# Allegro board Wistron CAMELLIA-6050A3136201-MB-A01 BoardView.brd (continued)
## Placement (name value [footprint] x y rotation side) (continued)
C4608  22uF_6.3V_3  [CLOONEY-6010B0219002-001]  143.28 68.92 270 top
C4609  22uF_6.3V_3  [CLOONEY-6010B0219002-001]  113.43 67.25 180 bottom
C4610  22uF_6.3V_3  [CLOONEY-6010B0219002-001]  140.84 68.92 270 top
C4611  22uF_6.3V_3  [CLOONEY-6010B0219002-001]  144.5 66.5 90 top
C4612  0.22uF_6.3V_1  [CSC_060X030X030_2]  253.62 14.94 90 top
C4613  0.22uF_6.3V_1  [CSC_060X030X030_2]  254.22 14.94 90 top
C4614  0.22uF_6.3V_1  [CSC_060X030X030_2]  250.62 14.94 90 top
C4615  0.22uF_6.3V_1  [CSC_060X030X030_2]  251.23 14.94 90 top
C4616  0.22uF_6.3V_1  [CSC_060X030X030_2]  251.89 56.05 270 top
C4617  0.22uF_6.3V_1  [CSC_060X030X030_2]  252.5 56.05 270 top
C4618  0.22uF_6.3V_1  [CSC_060X030X030_2]  254.94 56.05 270 top
C4619  0.22uF_6.3V_1  [CSC_060X030X030_2]  254.33 56.05 270 top
C4620  22uF_6.3V_3  [CLOONEY-6010B0219002-001]  145.81 64.15 270 top
C4621  22uF_6.3V_3  [CLOONEY-6010B0219002-001]  144.59 64.15 270 top
C4622  22uF_6.3V_3  [CLOONEY-6010B0219002-001]  145.72 66.5 90 top
C4623  22uF_6.3V_3  [CLOONEY-6010B0219002-001]  147.03 64.15 270 top
C4624  1uF_6.3V_1  [CSC_060X030X035_2]  166.34 77.3 0 top
C4625  10uF_6.3V_2  [CSC_100X050X070_2]  163.7 89.09 180 top
C4626  22uF_6.3V_3  [CSC_160X080X100_2]  166.7 76.39 0 top
C4627  0.1uF_6.3V_1  [CSC_060X030X030_2]  204.11 64.45 90 bottom
C4628  22uF_6.3V_3  [CLOONEY-6010B0219002-001]  152.83 69.38 270 top
C4629  22uF_6.3V_3  [CLOONEY-6010B0219002-001]  123.72 90.87 270 top
C4630  22uF_6.3V_3  [CLOONEY-6010B0219002-001]  154.78 63.89 180 top
C4631  22uF_6.3V_3  [CLOONEY-6010B0219002-001]  146.96 89.85 270 top
C4632  0.22uF_6.3V_1  [CSC_060X030X030_2]  256.77 56.05 270 top
C4633  0.22uF_6.3V_1  [CSC_060X030X030_2]  257.37 56.05 270 top
C4634  0.22uF_6.3V_1  [CSC_060X030X030_2]  259.23 56.05 270 top
C4635  0.22uF_6.3V_1  [CSC_060X030X030_2]  259.84 56.05 270 top
C4636  22uF_6.3V_3  [CLOONEY-6010B0219002-001]  154.78 69.98 180 top
C4637  22uF_6.3V_3  [CLOONEY-6010B0219002-001]  143.15 89.85 270 top
C4638  22uF_6.3V_3  [CLOONEY-6010B0219002-001]  154.78 68.76 180 top
C4639  22uF_6.3V_3  [CLOONEY-6010B0219002-001]  157.12 94.68 0 top
C4640  22uF_6.3V_3  [CLOONEY-6010B0219002-001]  144.42 89.85 270 top
C4641  22uF_6.3V_3  [CLOONEY-6010B0219002-001]  151.61 69.38 270 top
C4642  22uF_6.3V_3  [CLOONEY-6010B0219002-001]  157.12 93.41 0 top
C4643  22uF_6.3V_3  [CLOONEY-6010B0219002-001]  150.39 69.38 270 top
C4644  22uF_6.3V_3  [CLOONEY-6010B0219002-001]  145.69 89.85 270 top
C4645  22uF_6.3V_3  [CLOONEY-6010B0219002-001]  142.15 61.82 90 top
C4646  22uF_6.3V_3  [CLOONEY-6010B0219002-001]  147.03 61.82 90 top
C4647  22uF_6.3V_3  [CLOONEY-6010B0219002-001]  144.59 61.82 90 top
C4648  22uF_6.3V_3  [CLOONEY-6010B0219002-001]  145.81 61.82 90 top
C4649  10uF_6.3V_3  [RANGERS-6010B0044902-001]  143.37 61.82 90 top
C4650  0.1uF_6.3V_1  [CSC_060X030X030_2]  204.75 64.45 90 bottom
C4651  0.1uF_6.3V_1  [CSC_060X030X030_2]  74.34 28.39 0 bottom
C4652  0.1uF_6.3V_1  [CSC_060X030X030_2]  74.34 27.75 0 bottom
C4764  1uF_6.3V_1  [CSC_060X030X035_2]  222.48 53.05 90 bottom
C4766  1uF_6.3V_1  [CSC_060X030X035_2]  222.73 53.91 180 bottom
C4767  12pF_50V_1  [CSC_060X030X030_2]  204.06 49.57 90 bottom
C4768  1uF_6.3V_1  [CSC_060X030X035_2]  220.82 51.37 270 bottom
C4788  12pF_50V_1  [CSC_060X030X030_2]  204.06 50.71 270 bottom
C4818  0.22uF_6.3V_1  [CSC_060X030X030_2]  259.63 14.94 90 top
C4819  0.22uF_6.3V_1  [CSC_060X030X030_2]  260.24 14.94 90 top
C4820  0.22uF_6.3V_1  [CSC_060X030X030_2]  256.64 14.94 90 top
C4821  0.22uF_6.3V_1  [CSC_060X030X030_2]  257.25 14.94 90 top
C4826  15pF_25V_1  [CSC_060X030X033_2]  188.64 76.13 90 bottom
C4828  12pF_50V_1  [CSC_060X030X030_2]  188.64 74.98 270 bottom
C4920  1uF_6.3V_2_NP  [CSC_100X050X055_2_NP]  102.64 41.72 0 top
C4921  1uF_6.3V_2_NP  [CSC_100X050X055_2_NP]  99.46 41.72 0 top
C4937  0.1uF_10V_1  [CSC_060X030X030_2]  125.37 72.35 90 top
C6035  1000pF_25V_1  [CSC_060X030X030_2]  232 80.66 180 bottom
C6037  1000pF_25V_1  [CSC_060X030X030_2]  233.4 79.29 180 bottom
C6038  0.01UF_25V_1  [CSC_060X030X033_2]  234.51 79.37 180 bottom
C7000  1uF_6.3V_1  [CSC_060X030X035_2]  212.24 87.7 180 bottom
C7001  0.22uF_6.3V_1  [CSC_060X030X030_2]  214.27 93.79 180 bottom
C7002  1uF_6.3V_1  [CSC_060X030X035_2]  212.49 83.63 0 bottom
C7003  10uF_6.3V_3  [RANGERS-6010B0044902-001]  197.05 91.68 270 bottom
C7004  0.1uF_6.3V_1  [CSC_060X030X030_2]  211.1 87.7 180 bottom
C7005  10uF_6.3V_3  [RANGERS-6010B0044902-001]  209.7 87.44 270 bottom
C7006  0.1uF_6.3V_1  [CSC_060X030X030_2]  199.42 88.98 0 bottom
C7007  0.1uF_6.3V_1  [CSC_060X030X030_2]  211.35 83.63 0 bottom
C7008  10uF_6.3V_3  [RANGERS-6010B0044902-001]  208.52 84.27 180 bottom
C7009  0.01UF_25V_1  [CSC_060X030X033_2]  212.35 76.65 90 bottom
C7010  0.1uF_6.3V_1  [CSC_060X030X030_2]  195.73 94.15 180 bottom
C7012  0.1uF_6.3V_1  [CSC_060X030X030_2]  213.76 91.25 90 bottom
C7013  4.7uF_6.3V_3  [CSC_160X080X090_2]  215.29 91.25 0 bottom
C7023  0.1uF_25V_1  [CSC_060X030X033_2]  158.65 97.73 180 bottom
C7024  0.1uF_6.3V_1  [CSC_060X030X030_2]  208.73 76.77 90 bottom
C7025  3300pF_50V_2  [CSC_100X050X040_2]  161.41 87.06 90 bottom
C7027  0.01UF_25V_1  [CSC_060X030X033_2]  161.46 88.48 270 bottom
C7029  0.01uF_25V_2  [CSC_100X050X040_2]  169.19 42.23 90 top
C7040  220pF_50V_1  [CSC_060X030X033_2]  208.68 85.92 0 bottom
C7041  220pF_50V_1  [CSC_060X030X033_2]  208.68 85.28 180 bottom
C7400  0.01UF_25V_1  [CSC_060X030X033_2]  213.48 70.3 270 bottom
C7401  3300pF_50V_2  [CSC_100X050X040_2]  216.56 74.61 0 bottom
C7402  1000pF_25V_1  [CSC_060X030X030_2]  212.24 74.82 270 bottom
C7403  0.22uF_6.3V_1  [CSC_060X030X030_2]  208.02 73.6 90 bottom
C7406  1uF_6.3V_1  [CSC_060X030X035_2]  226.36 36.13 270 top
C7500  100pF_50V_1  [CSC_060X030X030_2]  85.95 28.11 270 bottom
C7501  100pF_50V_1  [CSC_060X030X030_2]  87.09 28.11 270 bottom
C7502  0.1uF_25V_2  [CSC_100X050X040_2]  86.05 24.83 0 bottom
C7503  100pF_50V_1  [CSC_060X030X030_2]  79.56 25.97 0 bottom
C7504  470PF_50V_1  [CSC_060X030X033_2]  267.2 47.56 180 bottom
C7505  18pF_50V_1  [CSC_060X030X030_2]  209.98 61.61 180 bottom
C7506  18pF_50V_1  [CSC_060X030X030_2]  208.86 61.61 0 bottom
C7507  18pF_50V_1  [CSC_060X030X030_2]  211.88 63.59 90 bottom
C7508  1uF_6.3V_1  [CSC_060X030X035_2]  229.13 7.94 0 top
C7511  68pF_50V_1  [CSC_060X030X033_2]  145.06 113.35 180 top
C7512  68pF_50V_1  [CSC_060X030X033_2]  148.49 5.65 0 top
C7513  68pF_50V_1  [CSC_060X030X033_2]  129.94 2.61 270 top
C7514  68pF_50V_1  [CSC_060X030X033_2]  189.38 99 0 top
C7515  68pF_50V_1  [CSC_060X030X033_2]  214.14 79.57 270 top
C7516  68pF_50V_1  [CSC_060X030X033_2]  122.7 113.35 0 top
C7517  68pF_50V_1  [CSC_060X030X033_2]  62.38 11.62 0 top
C7518  68pF_50V_1  [CSC_060X030X033_2]  155.85 2.35 0 top
C7519  68pF_50V_1  [CSC_060X030X033_2]  212.75 99.51 0 top
C7520  10pF_50V_1  [CSC_060X030X030_2]  57.81 32.96 0 bottom
C7521  68pF_50V_1  [CSC_060X030X033_2]  57.81 33.59 0 bottom
C7522  100pF_50V_1  [CSC_060X030X030_2]  57.81 32.32 0 bottom
C7523  10pF_50V_1  [CSC_060X030X030_2]  125.9 90.79 270 top
C7524  68pF_50V_1  [CSC_060X030X033_2]  126.51 90.79 270 top
C7525  100pF_50V_1  [CSC_060X030X030_2]  127.12 90.79 270 top
C7526  10pF_50V_1  [CSC_060X030X030_2]  135.3 90.79 270 top
C7527  68pF_50V_1  [CSC_060X030X033_2]  135.91 90.79 270 top
C7528  100pF_50V_1  [CSC_060X030X030_2]  136.52 90.79 270 top
C7529  10pF_50V_1  [CSC_060X030X030_2]  153.62 61.58 180 top
C7530  CSC0201  [CSC_060X030X030_2]  227 36.13 270 top
C7531  68pF_50V_1  [CSC_060X030X033_2]  153.62 60.97 180 top
C7532  100pF_50V_1  [CSC_060X030X030_2]  153.62 60.36 180 top
C7533  10pF_50V_1  [CSC_060X030X030_2]  145.31 111.26 180 bottom
C7534  68pF_50V_1  [CSC_060X030X033_2]  145.31 116.47 180 bottom
C7535  100pF_50V_1  [CSC_060X030X030_2]  145.31 110.66 180 bottom
C7536  6.8PF_50V_1  [CSC_060X030X033_2]  163.6 29.15 180 top
C7537  6.8PF_50V_1  [CSC_060X030X033_2]  217.32 21.53 90 top
C7538  6.8PF_50V_1  [CSC_060X030X033_2]  162.84 27.88 0 top
C7539  6.8PF_50V_1  [CSC_060X030X033_2]  142.01 55.56 180 top
C7540  6.8PF_50V_1  [CSC_060X030X033_2]  219.35 21.66 90 top
C7541  6.8PF_50V_1  [CSC_060X030X033_2]  175.54 21.53 90 top
C7542  6.8PF_50V_1  [CSC_060X030X033_2]  145.95 18.61 270 top
C7543  6.8PF_50V_1  [CSC_060X030X033_2]  183.41 23.18 270 top
C7544  6.8PF_50V_1  [CSC_060X030X033_2]  191.41 13.91 0 top
C7545  6.8PF_50V_1  [CSC_060X030X033_2]  97.81 23.43 270 top
C7546  6.8PF_50V_1  [CSC_060X030X033_2]  231.92 17.85 180 top
C7547  6.8PF_50V_1  [CSC_060X030X033_2]  149.37 11.88 270 top
C7548  6.8PF_50V_1  [CSC_060X030X033_2]  154.33 55.43 90 top
C7549  6.8PF_50V_1  [CSC_060X030X033_2]  143.28 21.53 90 top
C7550  6.8PF_50V_1  [CSC_060X030X033_2]  193.82 21.53 90 top
C7551  6.8PF_50V_1  [CSC_060X030X033_2]  187.6 21.66 90 top
C7552  6.8PF_50V_1  [CSC_060X030X033_2]  112.16 21.91 90 top
C7553  6.8PF_50V_1  [CSC_060X030X033_2]  225.07 21.4 90 top
C7554  6.8PF_50V_1  [CSC_060X030X033_2]  141.37 19.24 270 top
C7555  10pF_50V_1  [CSC_060X030X030_2]  182.52 103.95 270 bottom
C7556  68pF_50V_1  [CSC_060X030X033_2]  183.16 103.95 270 bottom
C7557  0.1uF_25V_1  [CSC_060X030X033_2]  183.79 103.95 270 bottom
C7558  10pF_50V_1  [CSC_060X030X030_2]  170.58 94.93 0 bottom
C7559  68pF_50V_1  [CSC_060X030X033_2]  170.58 95.57 0 bottom
C7560  100pF_50V_1  [CSC_060X030X030_2]  170.58 96.2 0 bottom
C7561  10pF_50V_1  [CSC_060X030X030_2]  115.44 89.14 225 bottom
C7562  68pF_50V_1  [CSC_060X030X033_2]  115.87 88.71 225 bottom
C7563  100pF_50V_1  [CSC_060X030X030_2]  116.3 88.28 225 bottom
C7564  100pF_50V_1  [CSC_060X030X030_2]  181.07 102.48 180 bottom
C7565  100pF_50V_1  [CSC_060X030X030_2]  181.07 101.87 180 bottom
C7566  100pF_50V_1  [CSC_060X030X030_2]  181.07 99.79 180 bottom
C7567  10pF_50V_1  [CSC_060X030X030_2]  228.01 86.32 0 bottom
C7568  68pF_50V_1  [CSC_060X030X033_2]  228.01 86.93 0 bottom
C7600  0.1uF_25V_2  [CSC_100X050X040_2]  272.16 33.21 270 top
C7601  0.1uF_25V_2  [CSC_100X050X040_2]  268.37 38.8 90 top
C7602  0.22uF_25V_1  [CSC_060X030X033_2]  269.14 38.55 90 top
C7603  0.22uF_25V_1  [CSC_060X030X033_2]  272.92 33.47 270 top
C7604  0.1uF_25V_2  [CSC_100X050X040_2]  274.72 93.92 90 top
C7605  0.1uF_25V_2  [CSC_100X050X040_2]  269.62 81.07 180 top
C7606  0.22uF_25V_1  [CSC_060X030X033_2]  273.96 93.92 90 top
C7607  0.22uF_25V_1  [CSC_060X030X033_2]  269.49 80.3 180 top
C7608  0.1uF_25V_2  [CSC_100X050X040_2]  199.92 97.6 90 top
C7609  0.1uF_25V_2  [CSC_100X050X040_2]  162.33 95.95 180 top
C7610  0.1uF_25V_2  [CSC_100X050X040_2]  103.65 6.92 0 top
C7611  0.1uF_10V_1  [CSC_060X030X030_2]  267.31 80.38 90 top
C7612  0.1uF_10V_1  [CSC_060X030X030_2]  215.29 53.15 270 top
C7613  0.1uF_10V_1  [CSC_060X030X030_2]  219.73 100.78 90 top
C7614  0.1uF_10V_1  [CSC_060X030X030_2]  55.27 22.67 90 top
C7615  0.1uF_10V_1  [CSC_060X030X030_2]  54.84 9.65 270 top
C7616  0.1uF_10V_1  [CSC_060X030X030_2]  200.68 115.38 0 top
C7617  0.1uF_10V_1  [CSC_060X030X030_2]  31.26 45.4 0 top
C7618  0.1uF_10V_1  [CSC_060X030X030_2]  267.61 86.17 0 top
C7619  0.1uF_10V_1  [CSC_060X030X030_2]  76.98 31.94 90 top
C7620  0.1uF_10V_1  [CSC_060X030X030_2]  26.31 21.53 90 top
C7621  0.1uF_10V_1  [CSC_060X030X030_2]  56.13 25.09 270 top
C7622  0.1uF_10V_1  [CSC_060X030X030_2]  238.12 28.01 0 top
C7623  0.01UF_25V_1  [CSC_060X030X033_2]  232.86 80.51 270 bottom
C7624  10pF_50V_1  [CSC_060X030X030_2]  24.56 33.26 270 top
C7625  10pF_50V_1  [CSC_060X030X030_2]  25.78 37.28 0 top
C7626  1000pF_25V_1  [CSC_060X030X030_2]  273.35 93.92 90 top
C7627  1000pF_25V_1  [CSC_060X030X030_2]  269.74 38.55 90 top
C7628  0.1uF_25V_2  [CSC_100X050X040_2]  251.1 93.03 90 bottom
C9200  0.1uF_16V_2  [CSC_100X050X040_2]  37.54 109.21 270 top
C9201  0.1uF_16V_2  [CSC_100X050X040_2]  42.21 104.21 180 top
C9202  0.1uF_16V_2  [CSC_100X050X040_2]  42.21 105.09 180 top
C9203  0.01uF_50V_2  [CSC_100X050X040_2]  35.96 101.16 90 top
C9204  0.1uF_16V_2  [CSC_100X050X040_2]  34.19 100.34 270 top
C9205  1uF_6.3V_2  [CSC_100X050X055_2]  35.07 101.16 90 top
C9206  10uF_6.3V_3  [CSC_160X080X095_2]  34.97 108.8 90 top
C9207  10uF_6.3V_3  [RANGERS-6010B0044902-001]  34.57 88.71 90 top
C9208  100uF_6.3V  [CST_320X160X180_2_245]  41.68 106.21 90 bottom
C9209  0.1uF_16V_2  [CSC_100X050X040_2]  37.78 89.09 90 top
C9210  0.1uF_16V_2  [CSC_100X050X040_2]  38.67 89.09 90 top
C9211  0.1uF_16V_2  [CSC_100X050X040_2]  41.17 89.22 90 top
C9212  0.1uF_16V_2  [CSC_100X050X040_2]  40.28 89.22 90 top
C9213  0.1uF_16V_2  [CSC_100X050X040_2]  35.71 88.33 90 top
C9214  0.1uF_16V_2  [CSC_100X050X040_2]  43.33 87.44 270 top
C9215  0.1uF_16V_2  [CSC_100X050X040_2]  42.44 87.44 270 top
C9216  0.01uF_50V_2  [CSC_100X050X040_2]  37.11 81.98 90 top
C9217  0.1uF_16V_2  [CSC_100X050X040_2]  38 81.98 90 top
C9218  1uF_6.3V_2  [CSC_100X050X055_2]  38.88 81.98 90 top
C9222  0.1uF_16V_2  [CSC_100X050X040_2]  40.18 69.92 90 top
C9223  0.1uF_16V_2  [CSC_100X050X040_2]  39.29 69.92 90 top
C9224  0.1uF_16V_2  [CSC_100X050X040_2]  41.07 69.92 90 top
C9225  0.1uF_16V_2  [CSC_100X050X040_2]  41.96 69.92 90 top
C9226  100pF_50V_1  [CSC_060X030X030_2]  27.15 74.08 270 top
C9227  100pF_50V_1  [CSC_060X030X030_2]  30.12 68.14 90 top
C9228  100pF_50V_1  [CSC_060X030X030_2]  30.1 73.88 90 top
C9229  0.1uF_10V_1  [CSC_060X030X030_2]  42.77 102.49 0 bottom
C9300  0.1uF_10V_1  [CSC_060X030X030_2]  77.14 108.42 180 top
C9301  0.1uF_10V_1  [CSC_060X030X030_2]  77.5 106.07 180 top
C9302  0.1uF_10V_1  [CSC_060X030X030_2]  75.34 79.06 0 top
C9353  4.7UF_6.3V_2  [CSC_100X050X065_2]  61.69 66.87 0 top
C9354  1000pF_25V_1  [CSC_060X030X030_2]  61.49 67.88 0 top
C9357  4.7UF_6.3V_2  [CSC_100X050X065_2]  61.57 65.98 0 top
C9360  1000pF_25V_1  [CSC_060X030X030_2]  60.6 64.58 0 top
C60000  68uF_16V  [CS_730X430X200_2_610]  145.02 113.86 180 bottom
C60001  4.7uF_25V_5  [CSC_200X125X135_2]  153.4 113.93 90 bottom
C60002  4.7uF_25V_5  [CSC_200X125X135_2]  151.75 113.93 90 bottom
C60003  2.2uF_25V_3  [CSC_160X080X095_2]  150.3 114.21 90 bottom
C60004  2.2uF_25V_3  [CSC_160X080X095_2]  154.84 116.04 90 bottom
C60006  0.022uF_16V_2  [CSC_100X050X040_2]  187.52 102.17 180 top
C60007  CSC0402  [CSC_100X050X040_2]  188.77 101.64 270 top
C60008  2.2UF_6.3V_2  [CSC_100X050X055_2]  184.05 108.78 270 top
C60009  4.7uF_25V_3  [CSC_160X080X095_2]  199.92 111.19 90 bottom
C60010  10UF_25V_5  [CSC_200X125X140_2]  183.16 109.03 90 bottom
C60011  4.7uF_25V_5  [CSC_200X125X135_2]  177.95 108.02 90 bottom
C60012  CSC0805  [CSC_200X125X130_2]  179.98 104.33 270 bottom
C60013  CSC0603  [CSC_160X080X080_2]  181.51 104.46 270 bottom
C60014  1uF_25V_3  [CSC_160X080X080_2]  178.33 104.33 270 bottom
C60015  0.22uF_25V_3  [CSC_160X080X080_2]  194.84 111.95 90 top
C60016  CSC0402  [CSC_100X050X040_2]  175.08 115.97 0 bottom
C60017  10UF_25V_5  [CSC_200X125X140_2]  113.56 114.75 90 bottom
C60018  CSC0402  [CSC_100X050X040_2]  199.03 100.4 270 top
C60019  CSC0402  [CSC_100X050X040_2]  196.24 99.89 180 top
C60020  0.022uF_16V_2  [CSC_100X050X040_2]  191.77 97.58 180 top
C60021  CSC0402  [CSC_100X050X040_2]  199.92 112.71 90 top
C60022  2.2UF_6.3V_3  [CSC_160X080X090_2]  196.11 111.95 90 top
C60023  1UF_25V_2  [CSC_100X050X055_2]  197.13 106.75 270 top
C60024  CSC0402  [CSC_100X050X040_2]  199.03 112.71 90 top
C60025  0.22uF_25V_3  [CSC_160X080X080_2]  197.13 110.17 0 top
C60026  CSC0402  [CSC_100X050X040_2]  157.38 116.27 180 top
C60027  1000PF_50V_2  [CSC_100X050X055_2]  193.82 97.6 0 top
C60028  1UF_25V_2  [CSC_100X050X055_2]  189.25 113.25 90 top
C60029  CSC0402  [CSC_100X050X040_2]  188.87 111.85 180 top
C60030  CSC0402  [CSC_100X050X040_2]  193.67 113.78 0 top
C60031  CSC0402  [CSC_100X050X040_2]  197.25 98.92 0 top
C60032  10UF_25V_5  [CSC_200X125X140_2]  115.21 114.75 90 bottom
C60033  CSC0402  [CSC_100X050X040_2]  190.45 98.87 270 top
C60034  1UF_25V_2  [CSC_100X050X055_2]  245.51 97.58 270 top
C60035  2.2UF_6.3V_3  [CSC_160X080X090_2]  180.95 111.8 180 top
C60048  1uF_25V_3  [CSC_160X080X080_2]  241.88 80.68 0 bottom
C60049  10pF_50V_2  [CSC_100X050X040_2]  188.62 103.06 180 top
C60050  CSC0402  [CSC_100X050X040_2]  86.05 25.77 0 bottom
C60099  15uF_25V  [CS_350X280X200_2]  180.5 110.14 90 bottom
C60101  22uF_6.3V_3  [CSC_160X080X100_2]  229 66.36 0 bottom
C60102  22uF_6.3V_3  [CSC_160X080X100_2]  229 70.17 0 bottom
C60103  22uF_6.3V_3  [CSC_160X080X100_2]  229 68.9 0 bottom
C60104  22uF_6.3V_3  [CSC_160X080X100_2]  229 67.63 0 bottom
C60109  1uF_6.3V_2  [CSC_100X050X055_2]  224.69 80.33 270 bottom
C60110  10UF_25V_5  [CSC_200X125X140_2]  228.01 85.18 0 bottom
C60111  4.7uF_25V_3  [CSC_160X080X095_2]  228.18 83.62 0 bottom
C60112  0.1uF_25V_2  [CSC_100X050X040_2]  228.03 82.29 0 bottom
C60115  0.1uF_16V_2  [CSC_100X050X040_2]  223.29 77.54 270 bottom
C60116  CSC0402  [CSC_100X050X040_2]  231.26 75.22 270 bottom
C60190  0.1uF_16V_2  [CSC_100X050X040_2]  231.21 79.72 0 bottom
C60191  1uF_6.3V_2  [CSC_100X050X055_2]  231.21 78.83 0 bottom
C60200  1000PF_50V_2  [CSC_100X050X055_2]  241.75 76.57 270 bottom
C60201  22UF_6.3V_5  [CSC_200X125X140_2]  239.43 63.4 270 bottom
C60202  22UF_6.3V_5  [CSC_200X125X140_2]  237.78 63.4 270 bottom
C60203  22UF_6.3V_5  [CSC_200X125X140_2]  236.13 63.4 270 bottom
C60204  22UF_6.3V_5  [CSC_200X125X140_2]  234.35 63.4 270 bottom
C60205  100uF_6.3V  [CST_320X160X180_2_245]  234.34 64 270 bottom
C60209  4.7UF_6.3V_2  [CSC_100X050X065_2]  241.8 72.66 0 bottom
C60210  10UF_25V_5  [CSC_200X125X140_2]  237.89 78.31 0 bottom
C60211  10uF_25V_3  [CSC_160X080X090_2]  237.89 79.75 0 bottom
C60212  0.1uF_25V_2  [CSC_100X050X040_2]  237.77 77.04 0 bottom
C60215  0.1uF_16V_2  [CSC_100X050X040_2]  233.58 71.69 0 bottom
C60216  CSC0402  [CSC_100X050X040_2]  233.58 70.8 180 bottom
C60217  4.7UF_6.3V_2  [CSC_100X050X065_2]  241.8 73.55 0 bottom
C60250  22UF_6.3V_5  [CSC_200X125X140_2]  191.46 86.73 270 bottom
C60251  22UF_6.3V_5  [CSC_200X125X140_2]  189.81 86.73 270 bottom
C60252  22UF_6.3V_5  [CSC_200X125X140_2]  185.57 86.73 270 bottom
C60253  22UF_6.3V_5  [CSC_200X125X140_2]  188.16 86.73 270 bottom
C60254  100uF_6.3V  [CST_320X160X180_2_245]  185.57 86.3 270 bottom
C60259  4.7UF_6.3V_2  [CSC_100X050X065_2]  192.5 96.23 270 bottom
C60260  4.7uF_25V_5  [CSC_200X125X135_2]  187.09 101.16 90 bottom
C60261  4.7uF_25V_5  [CSC_200X125X135_2]  185.32 101.16 90 bottom
C60262  0.1uF_25V_2  [CSC_100X050X040_2]  188.49 100.78 90 bottom
C60263  15uF_25V  [CS_350X280X200_2]  160.47 106.39 0 bottom
C60265  0.1uF_16V_2  [CSC_100X050X040_2]  185.82 96.33 0 bottom
C60266  CSC0402  [CSC_100X050X040_2]  184.43 91.25 270 bottom
C60280  4.7UF_6.3V_2  [CSC_100X050X065_2]  193.39 96.61 270 bottom
C60281  1000PF_50V_2  [CSC_100X050X055_2]  194.07 98.74 180 bottom
C60300  22uF_6.3V_3  [CSC_160X080X100_2]  170.33 3.09 270 bottom
C60301  22uF_6.3V_3  [CSC_160X080X100_2]  172.77 3.09 270 bottom
C60302  22uF_6.3V_3  [CSC_160X080X100_2]  167.94 8.27 180 bottom
C60303  CSC0603  [CSC_160X080X080_2]  171.55 3.09 270 bottom
C60304  CSC0603  [CSC_160X080X080_2]  173.99 3.09 270 bottom
C60309  1uF_6.3V_2  [CSC_100X050X055_2]  156.99 7.69 0 top
C60310  10uF_25V_3  [CSC_160X080X090_2]  152.88 6.16 90 bottom
C60311  10UF_25V_5  [CSC_200X125X140_2]  154.33 6.16 90 bottom
C60312  0.1uF_25V_2  [CSC_100X050X040_2]  155.67 6.19 90 bottom
C60313  10uF_25V_3  [CSC_160X080X090_2]  154.33 6.16 90 bottom
C60315  0.1uF_16V_2  [CSC_100X050X040_2]  161.52 1.72 0 bottom
C60316  CSC0402  [CSC_100X050X040_2]  165.96 8.12 0 bottom
C60348  CSC0402  [CSC_100X050X040_2]  159.01 1.67 0 bottom
C60350  22uF_6.3V_3  [CSC_160X080X100_2]  158.03 9.76 0 top
C60351  0.22uF_6.3V_2  [CSC_100X050X040_2]  158.65 7.69 180 top
C60400  22uF_6.3V_3  [CSC_160X080X100_2]  204.85 4.26 270 bottom
C60401  22uF_6.3V_3  [CLOONEY-6010B0219002-001]  203.58 4.26 270 bottom
C60405  22pF_50V_2  [CSC_100X050X040_2]  194.38 7.69 270 bottom
C60410  10uF_6.3V_3  [CSC_160X080X095_2]  192.78 3.75 0 bottom
C60500  22uF_6.3V_3  [CSC_160X080X100_2]  115.22 55.51 90 bottom
C60501  22uF_6.3V_3  [CSC_160X080X100_2]  116.44 54.8 90 bottom
C60502  22uF_6.3V_3  [CSC_160X080X100_2]  117.66 54.8 90 bottom
C60509  1uF_6.3V_2  [CSC_100X050X055_2]  102.71 51.07 270 bottom
C60510  10UF_25V_5  [CSC_200X125X140_2]  100.48 54.36 90 bottom
C60511  0.1uF_25V_2  [CSC_100X050X040_2]  101.83 54.38 90 bottom
C60515  0.1uF_16V_2  [CSC_100X050X040_2]  106.78 50.61 90 bottom
C60516  CSC0402  [CSC_100X050X040_2]  110.54 57.66 0 bottom
C60600  22uF_6.3V_3  [CSC_160X080X100_2]  117.62 94.81 45 bottom
C60601  22uF_6.3V_3  [CSC_160X080X100_2]  118.51 93.92 45 bottom
C60602  22uF_6.3V_3  [CSC_160X080X100_2]  114.2 89.35 225 bottom
C60603  CSC0603  [CSC_160X080X080_2]  112.42 91.12 225 bottom
C60604  CSC0603  [CSC_160X080X080_2]  113.31 90.24 225 bottom
C60609  4.7UF_6.3V_2  [CSC_100X050X065_2]  109.8 100.47 225 bottom
C60610  10UF_25V_5  [CSC_200X125X140_2]  104.16 104.33 45 bottom
C60611  CSC0805  [CSC_200X125X130_2]  102.89 105.6 45 bottom
C60612  0.1uF_25V_2  [CSC_100X050X040_2]  105.05 103.32 45 bottom
C60615  0.1uF_16V_2  [CSC_100X050X040_2]  106.45 97.98 45 bottom
C60616  CSC0402  [CSC_100X050X040_2]  110 92.9 315 bottom
C60620  220pF_50V_2  [CSC_100X050X040_2]  109.12 104.71 225 bottom
C60630  1uF_6.3V_2  [CSC_100X050X055_2]  110.26 102.17 315 bottom
C60900  22uF_6.3V_3  [CSC_160X080X100_2]  171.22 92.14 0 bottom
C60901  22uF_6.3V_3  [CSC_160X080X100_2]  171.22 90.87 0 bottom
C60902  22uF_6.3V_3  [CSC_160X080X100_2]  171.22 89.6 0 bottom
C60903  CSC0603  [CSC_160X080X080_2]  171.22 88.33 0 bottom
C60904  CSC0603  [CSC_160X080X080_2]  171.22 93.41 0 bottom
C60909  4.7UF_6.3V_2  [CSC_100X050X065_2]  168.68 98.85 270 bottom
C60910  10UF_25V_5  [CSC_200X125X140_2]  163.78 103.34 90 bottom
C60911  CSC0805  [CSC_200X125X130_2]  162.12 103.34 90 bottom
C60912  0.1uF_25V_2  [CSC_100X050X040_2]  165.07 103.21 90 bottom
C60915  0.1uF_16V_2  [CSC_100X050X040_2]  162.71 98.62 0 bottom
C60916  CSC0402  [CSC_100X050X040_2]  162.46 94.93 270 bottom
C60920  330pF_50V_2  [CSC_100X050X040_2]  169.54 101.84 270 bottom
C60930  1uF_6.3V_2  [CSC_100X050X055_2]  169.92 99.68 0 bottom
C61400  22uF_6.3V_3  [CSC_160X080X100_2]  173.76 92.14 180 bottom
C61401  22uF_6.3V_3  [CSC_160X080X100_2]  173.76 90.87 180 bottom
C61402  22uF_6.3V_3  [CSC_160X080X100_2]  173.76 89.6 180 bottom
C61409  1uF_6.3V_2  [CSC_100X050X055_2]  174.93 96.71 270 bottom
C61410  10UF_25V_5  [CSC_200X125X140_2]  178.07 100.43 0 bottom
C61411  0.1uF_25V_2  [CSC_100X050X040_2]  178.33 98.98 0 bottom
C61415  0.1uF_16V_2  [CSC_100X050X040_2]  174.39 93.83 270 bottom
C61416  CSC0402  [CSC_100X050X040_2]  183.03 91.25 270 bottom
C61700  10uF_6.3V_3  [CSC_160X080X095_2]  232.27 89.94 90 bottom
C61705  330pF_50V_2  [CSC_100X050X040_2]  227 92.04 180 bottom
C61710  4.7uF_6.3V_3  [CSC_160X080X090_2]  224.94 87.67 0 bottom
C66000  330uF_2V_9mR_Pana_-35%  [CS_730X430X210_2]  139.01 95.7 90 bottom
C66001  22uF_6.3V_3  [CSC_160X080X100_2]  134.39 90.87 270 top
C66002  22uF_6.3V_3  [CSC_160X080X100_2]  141.25 91.28 270 top
C66003  22uF_6.3V_3  [CSC_160X080X100_2]  162.02 63.88 0 top
C66004  22uF_6.3V_3  [CSC_160X080X100_2]  124.99 90.87 270 top
C66005  22uF_6.3V_3  [CSC_160X080X100_2]  140 91.28 270 top
C66010  10UF_25V_5  [CSC_200X125X140_2]  144.57 107.76 180 bottom
C66011  10uF_25V_3  [CSC_160X080X090_2]  144.57 106.31 180 bottom
C66012  10uF_25V_3  [CSC_160X080X090_2]  144.57 109.21 180 bottom
C66014  1uF_25V_3  [CSC_160X080X080_2]  146.99 100.9 0 bottom
C66015  0.1uF_25V_2  [CSC_100X050X040_2]  148.61 101.08 270 bottom
C66016  CSC0402  [CSC_100X050X040_2]  140.89 100.7 180 bottom
C66017  1uF_6.3V_2  [CSC_100X050X055_2]  148.61 102.73 90 bottom
C66020  10UF_25V_5  [CSC_200X125X140_2]  115.29 105.55 225 bottom
C66021  10uF_25V_3  [CSC_160X080X090_2]  116.33 104.51 225 bottom
C66022  CSC0603  [CSC_160X080X080_2]  114.22 106.62 225 bottom
C66024  1uF_25V_3  [CSC_160X080X080_2]  121.56 101.89 45 bottom
C66025  0.1uF_25V_2  [CSC_100X050X040_2]  123.06 102.67 315 bottom
C66026  CSC0402  [CSC_100X050X040_2]  118.26 96.97 45 bottom
C66027  1uF_6.3V_2  [CSC_100X050X055_2]  121.32 104.43 135 bottom
C66030  10UF_25V_5  [CSC_200X125X140_2]  125.9 105.07 225 bottom
C66031  10uF_25V_3  [CSC_160X080X090_2]  126.82 103.95 225 bottom
C66032  CSC0603  [CSC_160X080X080_2]  124.79 105.98 225 bottom
C66034  1uF_25V_3  [CSC_160X080X080_2]  132.23 101.67 45 bottom
C66035  0.1uF_25V_2  [CSC_100X050X040_2]  133.4 102.78 315 bottom
C66036  CSC0402  [CSC_100X050X040_2]  136.55 101.06 270 bottom
C66037  1uF_6.3V_2  [CSC_100X050X055_2]  132.14 103.92 135 bottom
C66100  CSC0402  [CSC_100X050X040_2]  99.08 89.98 90 top
C66101  CSC0402  [CSC_100X050X040_2]  106.32 92.65 270 top
C66107  150pF_50V_2  [CSC_100X050X040_2]  95.22 95.89 180 top
C66110  4.7UF_6.3V_2  [CSC_100X050X065_2]  105.31 96.71 270 top
C66111  1uF_6.3V_2  [CSC_100X050X055_2]  96.23 90.3 270 top
C66115  0.1uF_16V_2  [CSC_100X050X040_2]  104.97 92 0 top
C66160  1uF_6.3V_2  [CSC_100X050X055_2]  106.19 98.36 270 top
C66172  CSC0402  [CSC_100X050X040_2]  99.31 108.12 180 top
C66197  330pF_50V_2  [CSC_100X050X040_2]  105.31 100.01 90 top
C66199  33uF_16V  [CS_350X280X200_2]  148.7 107.41 0 bottom
C66299  33uF_16V  [CS_350X280X200_2]  113.03 108.55 225 bottom
C66300  330uF_2V_9mR_Pana_-35%  [CS_730X430X210_2]  121.34 60.83 0 bottom
C66301  CSC0603  [CSC_160X080X080_2]  149.26 65.63 0 top
C66302  CSC0603  [CSC_160X080X080_2]  149.04 61.44 0 top
C66303  CSC0603  [CSC_160X080X080_2]  149.04 62.66 0 top
C66304  CSC0603  [CSC_160X080X080_2]  113.43 65.98 180 bottom
C66305  CSC0603  [CSC_160X080X080_2]  113.43 68.52 180 bottom
C66310  10UF_25V_5  [CSC_200X125X140_2]  105.31 71.69 180 bottom
C66311  10uF_25V_3  [CSC_160X080X090_2]  105.36 70.17 180 bottom
C66312  CSC0603  [CSC_160X080X080_2]  104.42 76.77 180 bottom
C66314  1uF_25V_3  [CSC_160X080X080_2]  106.75 64.58 0 bottom
C66315  0.1uF_25V_2  [CSC_100X050X040_2]  109.06 65.8 0 bottom
C66316  CSC0402  [CSC_100X050X040_2]  111.81 68.19 90 bottom
C66317  1uF_6.3V_2  [CSC_100X050X055_2]  109.32 67.07 90 bottom
C66399  15uF_25V  [CS_350X280X200_2]  122.81 107.28 225 bottom
C66407  470pF_50V_2  [CSC_100X050X040_2]  95.22 96.79 0 top
C66472  CSC0402  [CSC_100X050X040_2]  100.07 106.72 0 top
C66599  33uF_16V  [CS_350X280X200_2]  104.77 74.49 180 bottom
C66600  22uF_6.3V_3  [CSC_160X080X100_2]  158.52 91.76 0 bottom
C66601  22uF_6.3V_3  [CSC_160X080X100_2]  158.52 90.49 0 bottom
C66607  39pF_50V_2  [CSC_100X050X040_2]  95.39 93.73 270 top
C66610  10UF_25V_5  [CSC_200X125X140_2]  153.1 105.05 180 bottom
C66614  1uF_25V_3  [CSC_160X080X080_2]  154.32 99.36 0 bottom
C66615  0.1uF_25V_2  [CSC_100X050X040_2]  155.98 99.51 270 bottom
C66616  CSC0402  [CSC_100X050X040_2]  150.26 101.41 180 bottom
C66617  1uF_6.3V_2  [CSC_100X050X055_2]  155.98 101.16 90 bottom
C66672  CSC0402  [CSC_100X050X040_2]  95.4 101.54 0 bottom
C66806  0.01uF_50V_2  [CSC_100X050X040_2]  106.78 102.81 90 top
C68052  3900pF_16V_2  [CSC_100X050X040_2]  209.14 113.53 270 bottom
C68098  0.22uF_6.3V_2  [CSC_100X050X040_2]  246.07 24.37 180 top
C68099  100pF_50V_2  [CSC_100X050X040_2]  248.28 26.3 270 top
C76020  100pF_50V_1  [CSC_060X030X030_2]  242.47 64.2 270 bottom
CN200  ACES_50506_01001_001_10P  [CRESCENT-6012B0240012-003]  59 6.5 180 bottom
CN300  P_TWO_196652_42041_3_42P  [FPC_PTWO_42_050_R_160]  37.54 9 180 bottom
CN301  ENTERY_6718K_Y08N_01L_8P  [FPC_ENTRY_8_050_R_100]  147 3.07 180 bottom
CN303  ACES_51536_00801_Q01_8P  [FPC_ACES_8_050_R_120_1]  107 5.8 180 bottom
CN366  ACES_50951_0084N_001_8P  [OLYMPIA-6026B0270301-004]  225.7 31.18 45 top
CN367  ACES_50950_0084N_001_8P  [SKT-BIOS_ACES_1015X1000X295]  231.74 52.93 0 bottom
CN375  I_PEX_20455_030E_14_30P  [WTB_IPEX_30_050_SMD_R_F_100_1]  257.55 38.47 0 bottom
CN550  ACES_50224_00401_001_4P  [WTB_ACES_4_100_SMD_R_M_295]  3.9 37.85 180 bottom
CN1300  LOTES_APCI0019_P003H_75P  [NGFF_LOTES_67_050_E_308]  65.7 26 270 bottom
CN1400  LOTES_APCI0018_P005H_75P  [NGFF_LOTES_67_050_B_305]  208 57.6 180 bottom
CN1451  FULLINHOPE_A0635_0001_7P  [SIM-N_FULHP_7_ST_138]  286.21 46.02 90 top
CN1951  LOTES_APCI0020_P003H_75P  [STALLONE-6026B0240301-004]  257.4 17.3 180 bottom
CN2200  ACES_51536_00801_Q01_8P  [FPC_ACES_8_050_R_120_1]  235 5.8 180 bottom
CN2500  HIROSE_FH34SRJ_30S_0_5SH_50_30P  [CAMELLIA-6012B1039001-001]  9 46.5 0 bottom
CN2501  ACES_50224_00601_001_6P  [WTB_ACES_6_100_SMD_R_M_295_2]  13 35.5 0 bottom
CN2700  ACES_50951_0084N_001_8P  [OLYMPIA-6026B0270301-004]  241.07 59.67 180 top
CN2701  ACES_51614_01501_002_15P  [FPC_ACES_15_050_R_100_2]  248.87 78.15 90 bottom
CN2800  SUYIN_020090HB024M51UZL_24P  [USB31_SYN_24_SMD_S_158_341]  283.75 79.33 90 top
CN2900  SUYIN_020090HB024M51UZL_24P  [USB31_SYN_24_SMD_S_158_341]  283.75 63.69 90 top
CN3000  ACES_51398_0407T_001_40P  [CAMELLIA-6012B0773101-009]  21.5 27.5 90 bottom
CN3001  ACES_50406_02001_Q01_20P  [WTB_ACES_20_050_SMD_V_F_140]  227 102.5 90 bottom
CN3150  T_CONN_16_A3940_1A03_A_19P  [HDMI_TCONN_19_RS_225_261]  284.05 97.85 270 bottom
CN4100  ARGOSY_D4AR0_26010_1P40_260P  [SAGE12-6026B0328101-004]  128.5 16.6 180 bottom
CN4125  ARGOSY_D4AR0_26010_1P40_260P  [SAGE12-6026B0328101-004]  204.2 16.6 180 bottom
CN4300  ENTERY_3802K_Q04N_07L_4P  [LADYLUCK-6012B0446101-002]  83 38.35 0 bottom
CN4350  HIROSE_FH52_15S_0_5SH_15P  [FPC_HRS_15_050_R_175]  224 4.7 180 bottom
CN4750  ENTERY_3703K_Q02N_11L_2P  [WTB_ENTRY_2_100_SMD_R_M_295]  210 3.8 180 bottom
CN4920  SAMTEC_BSH_030_01_L_D_A_TR_60P  [BTB_SAM_60_050_F_325]  117.55 66.89 90 top
CN4941  JOINT_F0504WRA_S_18PNLNK1G00L_18P  [BALOS-6012B0622401-002]  258.37 49.77 0 bottom
CN6000  ACES_50224_00701_001_7P  [WTB_ACES_7_100_SMD_R_M_295_2]  238.5 88.5 0 bottom
CN6050  ACES_50279_0090T_Q01_9P  [WTB_ACES_9_125_SMD_R_M_215]  81.1 18.1 180 bottom
CN9200  SINGATRON_2UB1757_000111F_9P  [USB3_SIGAT_9_DIP_RS_S_210_271]  30.2 103.6 90 bottom
CN9201  SINGATRON_2UB1757_000111F_9P  [USB3_SIGAT_9_DIP_RS_S_210_271]  30.2 83.7 90 bottom
CN9202  HIROSE_FH34SRJ_30S_0_5SH_50_30P  [CAMELLIA-6012B1039001-001]  40 69.5 180 bottom
CN9203  ACES_50224_00601_001_6P  [WTB_ACES_6_100_SMD_R_M_295_2]  43 81.5 180 bottom
CN9300  ACES_50696_0060M_002_6P  [CAMELLIA-6012B0856401-001]  80.1 100.27 90 top
CN9301  ACES_50696_0060M_002_6P  [CAMELLIA-6012B0856401-001]  80.1 94.59 90 top
CN9302  ACES_50696_0060M_002_6P  [CAMELLIA-6012B0856401-001]  79.11 81.5 180 top
CN9354  ACES_50696_0120M_002_12P  [CAMELLIA-6012B0430404-001]  61.49 51.3 90 top
CP1  EMI_STOP_SUL_15A8M_1P  [FGR_SOLDERING_560X134X151X015]  144.76 9.8 180 bottom
CP2  EMI_STOP_SUL_15A8M_1P  [FGR_SOLDERING_560X134X151X015]  128.25 9.8 180 bottom
CP3  EMI_STOP_SUL_15A8M_1P  [FGR_SOLDERING_560X134X151X015]  265.5 9.8 180 bottom
CP4  EMI_STOP_SUL_15A8M_1P  [FGR_SOLDERING_560X134X151X015]  96 9.8 180 bottom
CP5  EMI_STOP_SUL_15A8M_1P  [FGR_SOLDERING_560X134X151X015]  90 42.5 270 bottom
CP6  EMI_STOP_SUL_15A8M_1P  [FGR_SOLDERING_560X134X151X015]  194.62 9.8 180 bottom
CP7  EMI_STOP_SUL_15A8M_1P  [FGR_SOLDERING_560X134X151X015]  152.4 9.8 0 bottom
CP8  EMI_STOP_SUL_15A8M_1P  [FGR_SOLDERING_560X134X151X015]  174.3 9.8 180 bottom
CP10  EMI_STOP_SUL_15A8M_1P  [FGR_SOLDERING_560X134X151X015]  96 48.2 180 bottom
CP11  EMI_STOP_SUL_15A8M_1P  [FGR_SOLDERING_560X134X151X015]  200.21 48.2 180 bottom
CP12  EMI_STOP_SUL_15A8M_1P  [FGR_SOLDERING_560X134X151X015]  242.7 43.5 270 bottom
CP13  EMI_STOP_SUL_15A8M_1P  [FGR_SOLDERING_560X134X151X015]  122 48.2 180 bottom
CP17  EMI_STOP_SUL_15A8M_1P  [FGR_SOLDERING_560X134X151X015]  269.8 74.5 270 bottom
CP18  EMI_STOP_SUL_15A8M_1P  [FGR_SOLDERING_560X134X151X015]  269.8 15.5 270 bottom
CP19  EMI_STOP_SUL_15A8M_1P  [FGR_SOLDERING_560X134X151X015]  245 14.5 270 bottom
CP20  EMI_STOP_SUL_15A8M_1P  [FGR_SOLDERING_560X134X151X015]  245 43.5 270 bottom
CP21  EMI_STOP_SUL_15A8M_1P  [FGR_SOLDERING_560X134X151X015]  238 9.8 180 bottom
CP22  EMI_STOP_SUL_15A8M_1P  [FGR_SOLDERING_560X134X151X015]  242.7 19.5 270 bottom
CP23  EMI_STOP_SUL_15A8M_1P  [FGR_SOLDERING_560X134X151X015]  269.8 53.5 270 bottom
D300  LITEON_LTW_C195DSKS_5A_4P  [LED_LITON_V_150X160X055_S_YW]  287 112.6 270 top
D301  BAT54A  [DSOT23_290X130X110_3_095_P2]  46.5 29.15 90 bottom
D302  PANJIT_BAW56DW_SOT363_6P  [DSSOT363_200X125X110_6_065]  42.82 21.66 90 bottom
D303  PANJIT_BAW56DW_SOT363_6P  [DSSOT363_200X125X110_6_065]  42.82 19.12 90 bottom
D304  PANJIT_BAW56DW_SOT363_6P  [DSSOT363_200X125X110_6_065]  41.55 16.68 90 bottom
D500  AMC_AZ5125_01H_SOD523_2P  [DSOD523_120X080X070_2_150_P2]  10.31 45 90 top
D1000  BAT54C_30V_0_6A  [DS_292X130X110_3_190]  221.38 59.53 180 bottom
D1300  DIODE-BAT54-TAP-PHP  [DSOT23_290X130X110_3_095_P3]  54.05 28.77 270 bottom
D1302  DIODE-BAT54-TAP-PHP  [DSOT23_290X130X110_3_095_P3]  50.49 31.69 180 bottom
D1400  1N4148WS  [DSOD323_185X125X095_2_231]  199.92 50.48 0 bottom
D1401  AMAZING_AZ5B75_01B_R7G_2P  [DS_060X030X030_2_040]  269.85 45.34 270 top
D1402  AMAZING_AZ5B75_01B_R7G_2P  [DS_060X030X030_2_040]  269.22 47.61 270 top
D1404  AMAZING_AZ5B75_01B_R7G_2P  [DS_060X030X030_2_040]  269.85 46.48 90 top
D1405  AMAZING_AZ5B75_01B_R7G_2P  [DS_060X030X030_2_040]  269.85 44.27 90 top
D1410  DIODE-BAT54-TAP-PHP  [DSOT23_290X130X110_3_095_P3]  206.78 62.93 0 top
D1451  BAV99  [DSSOT23_290X130X110_3_095-2]  281.05 51.35 90 bottom
D2201  AMC_AZ5125_01H_SOD523_2P  [DSOD523_120X080X070_2_150_P2]  233.09 7.38 90 top
D2202  AMC_AZ5125_01H_SOD523_2P  [DSOD523_120X080X070_2_150_P2]  231.67 7.38 90 top
D2603  SEMTECH_RCLAMP2451ZATFT_2P  [DS_060X030X025_2_043]  285.79 64.14 0 bottom
D2604  SEMTECH_RCLAMP2451ZATFT_2P  [DS_060X030X025_2_043]  285.39 78.26 0 bottom
D2605  SEMTECH_RCLAMP2451ZATFT_2P  [DS_060X030X025_2_043]  281.45 78.83 0 bottom
D2606  AMAZING_AZ1143_04F_R7G_10P  [DS_250X100X055_10_050_P2]  276.8 78.79 90 top
D2611  SS3040HE  [DSSOD123_280X180X100_2]  260.72 39.49 90 top
D2612  SS3040HE  [DSSOD123_280X180X100_2]  269.74 92.37 180 top
D2614  AMAZING_AZ1143_04F_R7G_10P  [DS_250X100X055_10_050_P2]  275.4 65.44 90 top
D2615  SEMTECH_RCLAMP2451ZATFT_2P  [DS_060X030X025_2_043]  281.07 63.54 0 bottom
D2618  SEMTECH_RCLAMP2451ZATFT_2P  [DS_060X030X025_2_043]  285.76 62.63 0 bottom
D2619  SEMTECH_RCLAMP2451ZATFT_2P  [DS_060X030X025_2_043]  281.07 62.49 0 bottom
D2700  1N4148WS  [DSOD323_185X125X095_2_231]  246.94 65.93 90 top
D2806  SEMTECH_RCLAMP2451ZATFT_2P  [DS_060X030X025_2_043]  281.45 78.11 0 bottom
D2807  SEMTECH_RCLAMP2451ZATFT_2P  [DS_060X030X025_2_043]  285.39 79.89 0 bottom
D2813  AMAZING_AZ5B8S_01F_R7G_2P  [DESD_060X030X032_2_040]  276.39 75.67 270 top
D2814  AMAZING_AZ5B8S_01F_R7G_2P  [DESD_060X030X032_2_040]  276.39 76.74 90 top
D2815  AMAZING_AZ5B8S_01F_R7G_2P  [DESD_060X030X032_2_040]  276.39 81.87 90 top
D2816  AMAZING_AZ5B8S_01F_R7G_2P  [DESD_060X030X032_2_040]  276.39 80.8 270 top
D2817  AMAZING_AZ5B8S_01F_R7G_2P  [DESD_060X030X032_2_040]  276.7 75.67 270 bottom
D2818  AMAZING_AZ5B8S_01F_R7G_2P  [DESD_060X030X032_2_040]  276.7 76.74 90 bottom
D2819  AMAZING_AZ5B8S_01F_R7G_2P  [DESD_060X030X032_2_040]  276.7 81.87 90 bottom
D2820  AMAZING_AZ5B8S_01F_R7G_2P  [DESD_060X030X032_2_040]  276.7 80.8 270 bottom
D2900  AMAZING_AZ5B8S_01F_R7G_2P  [DESD_060X030X032_2_040]  275.33 62.35 270 top
D2901  AMAZING_AZ5B8S_01F_R7G_2P  [DESD_060X030X032_2_040]  275.33 63.41 90 top
D2902  AMAZING_AZ5B8S_01F_R7G_2P  [DESD_060X030X032_2_040]  274.29 68.52 90 top
D2903  AMAZING_AZ5B8S_01F_R7G_2P  [DESD_060X030X032_2_040]  274.29 67.45 270 top
D2904  AMAZING_AZ5B8S_01F_R7G_2P  [DESD_060X030X032_2_040]  274.89 62.35 270 bottom
D2905  AMAZING_AZ5B8S_01F_R7G_2P  [DESD_060X030X032_2_040]  274.89 63.41 90 bottom
D2906  AMAZING_AZ5B8S_01F_R7G_2P  [DESD_060X030X032_2_040]  274.29 68.52 90 bottom
D2907  AMAZING_AZ5B8S_01F_R7G_2P  [DESD_060X030X032_2_040]  274.29 67.45 270 bottom
D3001  BAT54C_30V_0_6A  [DS_292X130X110_3_190]  24.14 9.1 270 top
D4300  AMC_AZ5125_01H_SOD523_2P  [DSOD523_120X080X070_2_150_P2]  82.83 30.04 180 bottom
D4301  AMC_AZ5125_01H_SOD523_2P  [DSOD523_120X080X070_2_150_P2]  82.83 31.56 180 bottom
D4702  BAT54A  [DSOT23_290X130X110_3_095_P2]  199.79 67.12 90 bottom
D4750  BAT54C_30V_0_6A  [DS_292X130X110_3_190]  221.38 56.07 0 bottom
D4920  DIODE-BAT54-TAP-PHP_NP  [DSOT23_290X130X110_3_095_NP]  104.8 43.75 0 top
D6035  AMC_AZ4024_02S_3P  [DSOT23_290X130X115_3_095]  231.54 82.96 180 bottom
D7002  DIODE-BAT54-TAP-PHP  [DSOT23_290X130X110_3_095_P3]  214.27 75.88 0 bottom
D7400  BAT54A  [DSOT23_290X130X110_3_095_P2]  209.7 69.28 180 bottom
D7500  AMC_AZ5125_01H_SOD523_2P  [DSOD523_120X080X070_2_150_P2]  79.1 25.07 0 bottom
D7504  AMC_AZ5125_01H_SOD523_2P  [DSOD523_120X080X070_2_150_P2]  85.04 29.63 270 bottom
D7505  AMC_AZ5125_01H_SOD523_2P  [DSOD523_120X080X070_2_150_P2]  87.98 29.63 270 bottom
D9200  AMAZING_AZ1143_04F_R7G_10P  [DS_250X100X055_10_050_P2]  40.43 103.9 90 top
D9201  AMAZING_AZ1143_04F_R7G_10P  [DS_250X100X055_10_050_P2]  35.91 104.31 0 top
D9202  AMAZING_AZ1143_04F_R7G_10P  [DS_250X100X055_10_050_P2]  35.71 84.65 270 top
D9203  AMAZING_AZ1143_04F_R7G_10P  [DS_250X100X055_10_050_P2]  40.92 85.41 90 top
D9204  AMC_AZ5125_01H_SOD523_2P  [DSOD523_120X080X070_2_150_P2]  31.77 69.79 0 top
D9205  AMC_AZ5125_01H_SOD523_2P  [DSOD523_120X080X070_2_150_P2]  45.62 68.16 0 top
D9206  AMC_AZ5125_01H_SOD523_2P  [DSOD523_120X080X070_2_150_P2]  45.62 66.74 0 top
D60031  1N4148WS  [DSOD323_185X125X095_2_231]  201.83 113.22 180 bottom
D60097  1N4148WS  [DSOD323_185X125X095_2_231]  178.97 110.99 90 top
D60098  1N4148WS  [DSOD323_185X125X095_2_231]  185.06 111.83 270 top
D60099  BAT54C_30V_0_6A  [DS_292X130X110_3_190]  202.03 115.76 0 bottom
D68200  PANJIT_PDZ5.1B  [CHROMIA-6011B0197701-001]  248.43 28.94 180 top
F300  LITTELFUSE_0805L110ULYR  [FUSE_210X135X075_2_220]  107.59 4.13 0 top
F2200  LITTELFUSE_0805L110ULYR  [FUSE_210X135X075_2_220]  236.34 4.89 90 top
F2500  LITTELFUSE_0805L110ULYR  [FUSE_210X135X075_2_220]  42.44 36.39 90 bottom
F3000  LITTELFUSE_0805L110ULYR  [FUSE_210X135X075_2_220]  221.26 103.19 0 top
F3001  LITTELFUSE_0805L110ULYR  [FUSE_210X135X075_2_220]  218.34 107.38 270 top
F3002  LITTELFUSE_0805L110ULYR  [FUSE_210X135X075_2_220]  20.09 19.24 90 top
F3003  1.1A_24V  [ALOE20-6036B0188001-002]  54.17 13.58 180 bottom
F4350  LITTELFUSE_0805L110ULYR  [FUSE_210X135X075_2_220]  221.33 4.82 90 top
FIX1  FIX_MASK_0.8  [FIX_MASK_080]  104.16 109.67 0 top
FIX2  FIX_MASK_0.8  [FIX_MASK_080]  258.21 12 0 top
FIX3  FIX_MASK_0.8  [FIX_MASK_080]  257.96 27.62 180 bottom
FIX4  FIX_MASK_0.8  [FIX_MASK_080]  107.48 113.83 180 bottom
FIX5  FIX_MASK_0.8  [FIX_MASK_080]  54.63 5.53 0 top
FIX6  FIX_MASK_0.8  [FIX_MASK_080]  271.42 102.55 0 top
FIX7  FIX_MASK_0.8  [FIX_MASK_080]  36.85 40.32 180 bottom
FIX8  FIX_MASK_0.8  [FIX_MASK_080]  267.87 95.06 180 bottom
FIX9200  FIX_MASK_0.8  [FIX_MASK_080]  36.09 66.87 0 top
FIX9201  FIX_MASK_0.8  [FIX_MASK_080]  31.9 109.16 0 top
FIX9202  FIX_MASK_0.8  [FIX_MASK_080]  29.08 59.81 180 bottom
FIX9203  FIX_MASK_0.8  [FIX_MASK_080]  29.08 55.18 180 bottom
FIX9204  FIX_MASK_0.8  [FIX_MASK_080]  48.74 73.93 180 bottom
FIX9205  FIX_MASK_0.8  [FIX_MASK_080]  43.25 101.36 180 bottom
FIX9206  FIX_MASK_0.8  [FIX_MASK_080]  48.16 67.38 0 top
FIX9207  FIX_MASK_0.8  [FIX_MASK_080]  48.54 75 0 top
FIX9350  FIX_MASK_0.8  [FIX_MASK_080]  59.84 105.22 0 top
FIX9351  FIX_MASK_0.8  [FIX_MASK_080]  59.71 65.85 0 top
JACK9200  SINGATRON_2SJ3166_026111F_6P  [AUDIO_SIGAT_6_R_140_390_1]  25.1 67.95 270 top
L2700  DLM0QSN900HY2D  [LS_065X050X035_4_050]  263.46 55.34 90 bottom
L2701  CYNTEC_CMMB041B_R68MS  [LS_440X420X120_2_370]  260.12 76.75 90 top
L3000  MCF08062G900_T  [TRYPTICO-6014B0378101-001]  222.27 101.03 90 bottom
L4555  DLM0QSN900HY2D  [LS_065X050X035_4_050]  187.14 75.62 90 bottom
L6035  120OHM_25%_3A  [LS_160X080X095_2]  233.75 81.32 90 bottom
L6036  120OHM_25%_3A  [LS_160X080X095_2]  234.87 81.32 90 bottom
L7500  RFL11T2SA2AR  [LS_100X125X090_6]  35.81 34.43 270 bottom
L7501  RFL11T2SA2AR  [LS_100X125X090_6]  35.02 32.55 270 bottom
L7502  RFL11T2SA2AR  [LS_100X125X090_6]  35.81 30.67 270 bottom
L7503  RFL11T2SA2AR  [LS_100X125X090_6]  35.05 21.12 270 bottom
L9200  MCF08062G900_T  [SILVERBE-6014B0378101-002]  34.31 105.98 90 top
L9201  MCF08062G900_T  [SILVERBE-6014B0378101-002]  37.74 85.03 225 top
L60000  PCMB103T_1R0MS  [LS_1000X1000X300_4_P2]  165.04 113.14 180 bottom
L60100  PCMC063T-1R5MN  [LADYLUCK-6014B0026101-007]  227.34 74.73 270 bottom
L60200  PCMC063T-1R5MN  [LADYLUCK-6014B0026101-007]  239.04 68.72 270 bottom
L60250  PCMC063T_2R2MN  [LS_700X660X300_2_555]  188.59 92.18 270 bottom
L60300  CYN_PCMC063T_R68MN_4P  [LS_660X660X300_4_P3]  165.84 4.18 0 bottom
L60400  TAI_TECH_HPC4018B_2R2M  [LS_400X400X180_2_280]  200.78 5.27 0 bottom
L60500  CYN_PCMC063T_R68MN_4P  [LS_660X660X300_4_P3]  110.74 53.56 0 bottom
L60600  PCMC063T-1R5MN  [LADYLUCK-6014B0026101-007]  112.34 96.89 315 bottom
L60900  PCMC063T-1R5MN  [LADYLUCK-6014B0026101-007]  166.52 94.55 270 bottom
L61400  CYN_PCMC063T_R68MN_4P  [LS_660X660X300_4_P3]  178.99 91.22 270 bottom
L61700  TAI_TECH_HPC4018B_2R2M  [LS_400X400X180_2_280]  229.51 89.41 0 bottom
L66010  MAGIC_SRPG0603_R15M_AD_D98E  [LS_730X680X300_4]  145.06 95.57 270 bottom
L66020  MAGIC_SRPG0603_R15M_AD_D98E  [LS_730X680X300_4]  123.34 95.95 315 bottom
L66030  MAGIC_SRPG0603_R15M_AD_D98E  [LS_730X680X300_4]  132.99 95.77 270 bottom
L66310  MAGIC_SRPG0603_R15M_AD_D98E  [LS_730X680X300_4]  111.75 61.79 0 bottom
L66610  CYN_PCMB063T_R33MS_4P  [LS_660X660X300_4_P3]  153.62 94.63 270 bottom
MIC9350  KNOWLES_SPK0838HT4H_1_8P  [MICP_KNOW_8_100_2]  60.64 116.18 180 top
MIC9352  KNOWLES_SPK0838HT4H_1_8P  [MICP_KNOW_8_100_2]  60.64 44.62 0 top
NOREF  -  []  159.99 -0.8 0 top
NOREF#2  -  [unnamed#2]  278.03 241.62 0 top
NOREF#3  -  []  26 114.55 180 top
NOREF#4  -  []  242.85 0.98 0 top
NOREF#5  -  []  62.13 74.61 270 top
NOREF#6  -  []  45.5 103.7 90 top
NOREF#7  -  []  146.85 119.9 0 top
NOREF#8  -  [unnamed#2]  11.45 -1.46 0 top
NOREF#9  -  []  257.4 180.1 270 top
NOREF#10  -  []  89.89 238.8 0 top
NOREF#11  -  [unnamed#3]  22.39 55.4 0 top
NOREF#12  -  []  167.58 37.46 0 top
NOREF#13  -  []  38.1 137.68 0 top
NOREF#14  -  [unnamed#3]  5 -0.3 0 top
NOREF#15  -  []  76.63 83.56 0 top
NOREF#16  -  [unnamed#3]  283.9 240.1 0 top
NOREF#17  -  []  134.9 240.6 0 top
NOREF#18  -  []  270.9 191.3 0 top
NOREF#19  -  []  52.25 238.83 0 top
NOREF#20  -  [unnamed#4]  104 113.5 90 top
NOREF#21  -  []  28.06 52.49 0 top
NOREF#22  -  []  83.92 120.39 0 top
NOREF#23  -  []  1.6 61.91 0 top
NOREF#24  -  []  4.9 209.6 180 top
NOREF#25  -  []  204.39 27.08 0 top
NOREF#26  -  []  257.04 102.07 0 top
NOREF#27  -  []  223.9 237.3 0 top
NOREF#28  -  []  60.47 89.09 270 top
NOREF#29  -  [unnamed#3]  274.74 70.68 0 top
NOREF#30  -  []  175.9 240.6 0 top
NOREF#31  -  []  214.07 163.79 0 top
NOREF#32  -  []  119 -0.8 0 top
NOREF#33  -  [unnamed#5]  59.74 107.75 0 top
NOREF#34  -  []  224.9 128.16 270 top
NOREF#35  -  []  117.55 119.9 0 top
NOREF#36  -  []  267.18 187.31 0 top
NOREF#37  -  []  11.71 284.09 0 top
NOREF#38  -  []  13.08 28.49 0 top
NOREF#39  -  []  51 79.7 90 top
NOREF#40  -  []  24 48.5 0 top
NOREF#41  -  [unnamed#3]  283.9 -0.3 0 top
NOREF#42  -  []  81.6 95.19 270 top
NOREF#43  -  []  198.23 237.28 0 top
NOREF#44  -  []  281.63 211.29 0 top
NOREF#45  -  []  204.9 0.98 0 top
NOREF#46  -  []  231.52 138.17 90 top
NOREF#47  -  []  57.38 107.53 90 top
NOREF#48  -  []  6.49 124.1 180 top
NOREF#49  -  [unnamed#3]  59.74 60.9 0 top
NOREF#50  -  []  224.9 176.79 270 top
NOREF#51  -  []  80.03 75.96 0 top
NOREF#52  -  []  105.4 240.6 0 top
NOREF#53  -  []  74.6 102.05 270 top
NOREF#54  -  []  285.32 30.16 0 top
NOREF#55  -  []  197.1 154.3 90 top
NOREF#56  -  [unnamed#3]  208 107.85 0 top
NOREF#57  -  []  63.19 111.62 90 top
NOREF#58  -  []  60.98 98.74 270 top
NOREF#59  -  []  214.3 137.41 90 top
NOREF#60  -  []  181.22 25.23 0 top
NOREF#61  -  [unnamed#4]  281.5 87.25 0 top
NOREF#62  -  [unnamed#3]  21.39 93.65 0 top
NOREF#63  -  []  189.5 -0.8 0 top
NOREF#64  -  []  216.35 156.3 0 top
NOREF#65  -  []  282.95 115.71 0 top
NOREF#66  -  []  134.64 30.55 0 top
NOREF#67  -  []  91.8 114.5 90 top
NOREF#68  -  []  57.38 61.94 90 top
NOREF#69  -  []  211.15 119.37 0 top
NOREF#70  -  []  197.1 125.3 270 top
NOREF#71  -  []  63.17 62.9 90 top
NOREF#72  -  []  237.9 166.1 90 top
NOREF#73  -  [unnamed#3]  78.94 100.1 90 top
NOREF#74  -  []  258.39 125.25 180 top
NOREF#75  -  []  177.33 119.9 0 top
NOREF#76  -  []  31.5 59.7 90 top
NOREF#77  -  []  71 2.5 0 top
NOREF#78  -  []  263.2 -0.8 0 top
NOREF#79  -  []  207.3 144.81 90 top
NOREF#80  -  []  91.8 85.5 270 top
NOREF#81  -  [unnamed#3]  277.7 32.58 0 top
NOREF#82  -  [unnamed#3]  97.51 79.5 0 top
NOREF#83  -  [unnamed#3]  274.74 33.25 0 top
NOREF#84  -  []  243.4 142.1 90 top
NOREF#85  -  []  25.7 240.6 180 top
NOREF#86  -  []  231.52 177.97 270 top
NOREF#87  -  []  98.6 5.3 0 top
NOREF#88  -  []  34.19 95.32 270 bottom
NOREF#89  -  []  43.45 94.93 270 bottom
NOREF#90  -  []  274.55 241.76 180 bottom
NOREF#91  -  []  15.06 -1.47 0 bottom
NOREF#92  -  []  79.15 109.45 270 bottom
NOREF#93  -  []  277.52 42.33 180 bottom
NOREF#94  -  []  81.1 77.66 180 bottom
NOREF#95  -  []  79.94 97.08 270 bottom
NOREF#96  -  []  39.14 100.52 180 bottom
PAD300  POWERPAD1x1m  [POWERPAD1X1M]  242.47 23.31 180 top
PAD310  POWERPAD1x1m  [POWERPAD1X1M]  250.11 39.82 180 top
PAD60000  -  [POWERPAD_2_0610]  151.89 110.73 180 bottom
PAD60100  POWERPAD_4_0610  [POWERPAD_4_0610_SHORT]  226.5 64.95 270 bottom
PAD60110  -  [POWERPAD_2_0610]  224.56 84.7 0 bottom
PAD60200  POWERPAD_4_0610  [POWERPAD_4_0610_SHORT]  232.57 63.25 180 bottom
PAD60210  POWERPAD1x1m  [POWERPAD1X1M]  235.43 77.89 0 bottom
PAD60250  POWERPAD_4_0610  [POWERPAD_4_0610_SHORT]  193.69 87.91 0 bottom
PAD60260  -  [POWERPAD_2_0610]  182.39 100.89 0 bottom
PAD60300  POWERPAD_4_0610  [POWERPAD_4_0610_SHORT]  172.83 5.55 90 bottom
PAD60310  -  [POWERPAD_2_0610]  153.54 2.5 90 bottom
PAD60350  POWERPAD1x1m  [POWERPAD1X1M]  160.55 9.21 0 top
PAD60400  POWERPAD1x1m  [POWERPAD1X1M]  205.64 6.67 0 bottom
PAD60410  POWERPAD1x1m  [POWERPAD1X1M]  192.79 5.53 270 bottom
PAD60500  POWERPAD1x1m  [POWERPAD1X1M]  116.06 52.42 0 bottom
PAD60510  POWERPAD1x1m  [POWERPAD1X1M]  98.52 53.28 0 bottom
PAD60600  POWERPAD_4_0610  [POWERPAD_4_0610_SHORT]  116.58 91.53 315 bottom
PAD60610  -  [POWERPAD_2_0610]  102.2 100.23 45 bottom
PAD60900  POWERPAD_4_0610  [POWERPAD_4_0610_SHORT]  166.92 89.74 270 bottom
PAD60910  -  [POWERPAD_2_0610]  159.28 102.94 0 bottom
PAD61410  POWERPAD1x1m  [POWERPAD1X1M]  175.59 100.67 0 bottom
PAD61499  POWERPAD2x2M  [POWERPAD2X2M]  173.96 88.08 270 bottom
PAD61710  POWERPAD1x1m  [POWERPAD1X1M]  222.15 89.98 0 bottom
PAD61799  POWERPAD1x1m  [POWERPAD1X1M]  231.57 86.06 0 bottom
PAD66010  -  [POWERPAD_2_0805]  148.43 109.95 180 bottom
PAD66020  -  [POWERPAD_2_0805]  118.26 107.89 225 bottom
PAD66030  -  [POWERPAD_2_0805]  120.8 110.68 45 bottom
PAD66310  -  [POWERPAD_2_0805]  104.29 78.89 270 bottom
PAD66610  -  [POWERPAD_2_0805]  156.36 105.09 180 bottom
Q300  PM513BA  [TSOT23_292X130X120_3_095]  131.17 6.35 180 bottom
Q301  TOSHIBA_SSM3K15AMFV_3P  [SOT723_120X080X055_3_040_P3]  130.91 3.62 180 bottom
Q302  TOSHIBA_SSM3K15AMFV_3P  [SOT723_120X080X055_3_040_P3]  225.07 37.28 270 top
Q303  PJX138K  [SOT563_160X120X060_6_050_P3]  46.43 19.45 270 bottom
Q305  PJX138K  [SOT563_160X120X060_6_050_P3]  49.68 19.62 180 bottom
Q307  PJX138K  [SOT563_160X120X060_6_050_P3]  214.02 4.51 180 bottom
Q500  TOSHIBA_SSM3K15AMFV_3P  [SOT723_120X080X055_3_040_P3]  12.8 42.69 0 top
Q1000  TOSHIBA_SSM3K15AMFV_3P  [SOT723_120X080X055_3_040_P3]  241.4 26.61 90 top
Q1001  PJX138K  [SOT563_160X120X060_6_050_P3]  214.55 46.22 0 top
Q1002  PJX138K  [SOT563_160X120X060_6_050_P3]  214.65 99.89 180 bottom
Q1003  TOSHIBA_SSM3K15AMFV_3P  [SOT723_120X080X055_3_040_P3]  238.5 26.63 270 top
Q1004  TOSHIBA_SSM3K15AMFV_3P  [SOT723_120X080X055_3_040_P3]  260.37 2 270 bottom
Q1300  TOSHIBA_SSM3K15AMFV_3P  [SOT723_120X080X055_3_040_P3]  75.71 38.04 270 bottom
Q1301  L2N7002SWT1G  [SC70_200X125X100_3_065]  50.14 24.25 0 bottom
Q1302  TOSHIBA_SSM3K15AMFV_3P  [SOT723_120X080X055_3_040_P3]  56.66 27.88 90 bottom
Q1304  L2N7002SWT1G  [SC70_200X125X100_3_065]  58.19 30.8 90 bottom
Q1307  DIODES_DMP2035UVT_7_TSOT26_6P  [TSOT26_290X160X100_6_095]  54.87 32.78 180 bottom
Q1400  TOSHIBA_SSM3K15AMFV_3P  [SOT723_120X080X055_3_040_P3]  223.01 51.3 270 bottom
Q1401  TOSHIBA_SSM3K15AMFV_3P  [SOT723_120X080X055_3_040_P3]  211.33 56.39 90 top
Q1951  TOSHIBA_SSM3K15AMFV_3P  [SOT723_120X080X055_3_040_P3]  259.99 11.75 90 top
Q2600  SYNNEX_SM3303PSQG  [MOSFET_300X300X100_8_065]  270.35 83.52 90 top
Q2601  LES_LBSS84LT1G_SOT23_3P  [TSSOT23_292X130X111_3_095]  257.78 44.34 180 top
Q2602  TOSHIBA_SSM3K15AMFV_3P  [SOT723_120X080X055_3_040_P3]  267.76 99.02 180 top
Q2603  LES_LBSS84LT1G_SOT23_3P  [TSSOT23_292X130X111_3_095]  262.15 93.05 180 top
Q2605  PJX138K  [SOT563_160X120X060_6_050_P3]  263.42 97.63 270 top
Q2607  PJX138K  [SOT563_160X120X060_6_050_P3]  256.44 48.22 0 top
Q2609  SYNNEX_SM3303PSQG  [MOSFET_300X300X100_8_065]  256.9 38.3 90 top
Q2613  TOSHIBA_SSM3K15AMFV_3P  [SOT723_120X080X055_3_040_P3]  266.37 39.62 90 top
Q2620  PJX138K  [SOT563_160X120X060_6_050_P3]  218.21 55.18 180 top
Q2701  PJX138K  [SOT563_160X120X060_6_050_P3]  249.91 71.16 180 top
Q3000  PM513BA  [TSOT23_292X130X120_3_095]  20.69 13.52 0 top
Q3001  PJX138K  [SOT563_160X120X060_6_050_P3]  22.2 17.26 0 top
Q3003  TOSHIBA_SSM3K15AMFV_3P  [SOT723_120X080X055_3_040_P3]  24.91 21.78 180 top
Q3004  TOSHIBA_SSM3K15AMFV_3P  [SOT723_120X080X055_3_040_P3]  23.91 12.35 270 top
Q3005  PJX138K  [SOT563_160X120X060_6_050_P3]  23.76 14.86 270 top
Q3800  PJX138K  [SOT563_160X120X060_6_050_P3]  194.48 73.33 270 top
Q4300  PJX138K  [SOT563_160X120X060_6_050_P3]  87.27 32.58 270 bottom
Q4411  PJX138K  [SOT563_160X120X060_6_050_P3]  127.15 85.28 180 bottom
Q4412  LMBT3904LT1G  [TSSOT23_292X130X111_3_096]  166.34 44.9 270 bottom
Q4750  PJX138K  [SOT563_160X120X060_6_050_P3]  198.9 62.93 180 top
